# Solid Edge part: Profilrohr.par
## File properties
Username: bmolnar
Dokumentum tartalom típus: 0
Author: bmolnar
Last saved by: bmolnar
Revision: 81
Sűrűség: 0,000 kg/m^3
Pontosság: 0,990
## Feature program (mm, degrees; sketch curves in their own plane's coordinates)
base feature "unnamed BaseFeature 1"
thread "unnamed Thread 1"
thread "Menet_2"  ThreadDepth = 5.5 mm
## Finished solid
Body 1: solid body, 127 faces, 307 edges, 198 vertices.
  Faces by surface: cylinder 57, plane 52, cone 16, torus 2
  Edges by curve: line 144, circle 142, spline 9, curve on surface 7, intersection 5
Bounding box of the edges (mm; curved faces can reach further): 30.000 x 34.000 x 63.000, from (-15, -15, 0) to (15, 19, 63).
Cylindrical faces by radius (mm): R0.3 x24, R0.65 x2, R1.85 x4, R2 x2, R2.067 x4, R2.35 x2, R2.8 x4, R3.75 x4, R8 x1, R8.95 x2, R9.1 x2, R9.5 x2, R20 x4
Conical faces (half-angle, radius in mm at the cone's reference point): 45 deg R2.317 x2, 45 deg R2.95 x4, 45 deg R3.9 x4, 45 deg R8.4 x2, 45 deg R9.2 x2, 45 deg R9.25 x2
Toroidal faces (ring radius, tube radius in mm): R9.4 r0.1 x2
Planar faces by outward normal: +x 6, +y 9, +z 9, -x 6, -y 5, -z 9, oblique 8
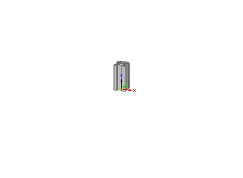
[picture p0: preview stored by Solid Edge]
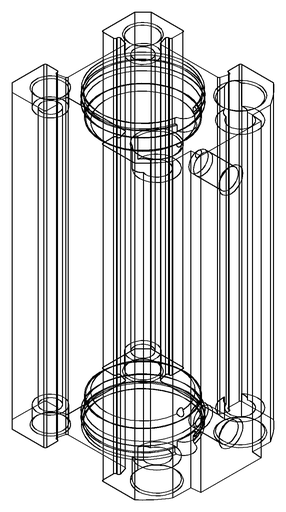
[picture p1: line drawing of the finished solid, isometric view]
